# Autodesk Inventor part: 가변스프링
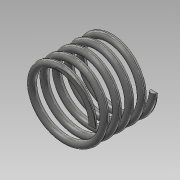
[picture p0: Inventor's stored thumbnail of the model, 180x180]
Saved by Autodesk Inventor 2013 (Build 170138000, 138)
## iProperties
Created: 2019-01
Part Number: 가변스프링
Material: 스테인리스강
Document SubType Name: Modeling
Designer: Administrator
Density: 8.08 g/cm^3
Mass: 7.81385 g
Surface Area: 19.6267 cm^2
Volume: 0.967061 cm^3
Author: Administrator
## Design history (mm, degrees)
sketch "스케치1"
  geometry: L1 (0, 0)-(10, 0); L2 (10, 0)-(10, 18.7); L3 (10, 18.7)-(0, 18.7); L4 (0, 18.7)-(0, 0); C1 r 1 at (10, 0)
  constraints: 8 end point, 2 parallel, 1 centre point, 1 coincident, 1 horizontal, 1 perpendicular
  dimensions: "d0" = 18.7 distance of L3.end L1.start (derived); "d1" = 2 diameter of C1; "d2" = 20 diameter of L2 L4
feature "코일1" pitch "d3" = 10; turns "d5" = 5; dims "d4" = 18.7 (= d0), "d6" = 0, angle "d7" = 90 deg, angle "d8" = 90 deg, "d9" = 0, "d10" = 0
sketch "스케치2"
  geometry: L1 (-9, 0)-(-11, 0) reference; 1 further point
  constraints: 1 horizontal alignment
extrude "돌출1" cut sketch "스케치2" stored distance "d11" = 10; taper "d12" = 0 deg
node "작업 평면1"
sketch "스케치3"
  geometry: L1 (-1, 0)-(1, 0) reference; 1 further point
  constraints: 1 horizontal alignment
extrude "돌출2" cut sketch "스케치3" stored distance "d14" = 10; taper "d15" = 0 deg
node "솔리드1"
node "절단 모서리 투영1"
node "절단 모서리 투영2"
other parameters: "d13" = 90 deg
